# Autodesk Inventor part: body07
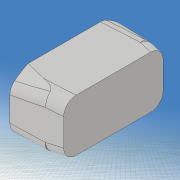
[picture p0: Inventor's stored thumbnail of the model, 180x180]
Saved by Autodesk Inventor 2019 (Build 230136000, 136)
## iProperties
Created: 2020-12
Part Number: body07
Material: 一般
Document SubType Name: Modeling
Designer: kikut
Density: 1 g/cm^3
Appearance: 既定
Mass: 87.6477 g
Surface Area: 156.124 cm^2
Volume: 87.6477 cm^3
Author: kikut
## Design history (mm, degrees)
sketch "スケッチ1"
  geometry: L1 (-100, -20)-(100, -20); L2 (100, -20)-(100, 20); L3 (100, 20)-(-100, 20); L4 (-100, 20)-(-100, -20); L5 (-100, -20)-(100, 20); L6 (100, -20)-(-100, 20); 1 further point
  constraints: 12 end point, 2 midpoint, 2 parallel, 1 horizontal, 1 perpendicular
  dimensions: "d0" = 40 distance of L3.end L1.start; "d1" = 200 distance of L2.end L3.end
extrude "押し出し1" new body sketch "スケッチ1" stored distance "d2" = 60; taper "d3" = 0 deg
sketch "スケッチ2"
  geometry: L1 (0, -60)-(0, 0) reference; L2 (200, -60)-(200, 0) reference; L3 (0, 0)-(200, 0) reference; L4 (200, -60)-(0, -60) reference; L5 (0, -26)-(0, -32); L6 (194, -10)-(194, -13); L7 (194, -13)-(174, -33); L8 (174, -33)-(200, -58); L9 (-20, 20)-(220, 20); L10 (220, 20)-(220, -100); L11 (220, -100)-(-20, -100); L12 (-20, -100)-(-20, 20); 12 further points
  constraints: 16 end point, 4 point on line, 2 parallel, 2 vertical, 1 horizontal, 1 perpendicular, 14 other
  dimensions: "d4" = 32 distance from line of point (32, -12) L1; "d5" = 50 horizontal distance of point (32, -12) point (82, -11); "d6" = 50 horizontal distance of point (132, -17) point (82, -11); "d7" = 12 distance from line of point (32, -12) L3; "d8" = 11 distance from line of point (82, -11) L3; "d10" = 17 distance from line of point (132, -17) L3; "d11" = 26 distance from line of L5.start L3; "d12" = 0 distance from line of point (200, -60) L4; "d13" = 28 distance from line of L5.end L4; "d14" = 12 distance from line of point (28, -48) L4; "d15" = 10 distance from line of point (80, -50) L4; "d16" = 16 distance from line of point (130, -44) L4; "d17" = 28 distance from line of point (28, -48) L1; "d19" = 50 horizontal distance of point (130, -44) point (80, -50); "d20" = 80 distance from line of point (80, -50) L1; "d21" = 6 distance from line of L6.start L2; "d22" = 36 distance from line of point (164, -24) L2; "d23" = 24 distance from line of point (176, -20) L2; "d24" = 10 distance from line of L6.start L3; "d25" = 20 distance from line of point (176, -20) L3; "d26" = 24 distance from line of point (164, -24) L3; "d27" = 40 distance from line of point (160, -40) L2; "d28" = 25 distance from line of point (175, -47.5) L2; "d29" = 12.5 distance from line of point (175, -47.5) L4; "d30" = 20 distance from line of L4 point (160, -40); "d31" = 3 distance of L6.start L6.end; "d32" = 33 distance from line of L7.end L3; "d33" = 26 distance from line of L7.end L2; "d34" = 2 distance of L8.end L2.start; "d35" = 120 distance of L11.end L9.start; "d36" = 240 distance of L10.end L11.end; "d37" = 20 distance between parallel lines of L1 L12; "d38" = 20 distance between parallel lines of L3 L9
extrude "押し出し2" cut sketch "スケッチ2" extent not by distance; stored distance "d39" = 0.02; taper "d40" = 0 deg
sketch "スケッチ8"
  geometry: L1 (-100, -20)-(-100, 20) reference; L2 (100, 20)-(100, -20) reference; L3 (-142.805, 0)-(142.831, 0) reference; L4 (110, 30)-(-110, 30); L5 (-110, 30)-(-110, -30); L6 (-110, -30)-(110, -30); L7 (110, -30)-(110, 30); L8 (110, 30)-(-110, -30); L9 (-110, 30)-(110, -30); L10 (-100, -2)-(-100, 2); L11 (100, -3)-(100, 3); 7 further points
  constraints: 16 end point, 4 point on line, 2 midpoint, 2 parallel, 2 perpendicular, 1 collinear, 1 horizontal, 10 other
  dimensions: "d93" = 2 vertical distance of point (0, 0) L10.end; "d94" = 2 vertical distance of L10.start point (0, 0); "d95" = 35 distance from line of point (-65, -10) L1; "d96" = 0 horizontal distance of point (-65, 10) point (-65, -10); "d97" = 10 vertical distance of point (0, 0) point (-65, -10); "d98" = 10 vertical distance of point (-65, 10) point (0, 0); "d99" = 100 distance from line of point (0, -10) L1; "d100" = 0 horizontal distance of point (0, 10) point (0, -10); "d101" = 10 distance of point (0, -10) point (0, 0); "d102" = 10 distance of point (0, 0) point (0, 10); "d103" = 160 distance from line of point (60, -4) L1; "d104" = 0 horizontal distance of point (60, 4) point (60, -4); "d105" = 4 distance from line of L3 point (60, -4); "d106" = 4 distance from line of L3 point (60, 4); "d107" = 3 distance from line of L11.start L3; "d108" = 3 distance from line of L11.end L3; "d109" = 220 distance of L5.end L6.end; "d110" = 60 distance of L4.end L5.end
extrude "押し出し6" cut sketch "スケッチ8" extent not by distance; stored distance "d111" = 10; taper "d112" = 0 deg
sketch "スケッチ9" dims "d113" = 20, "d114" = 12
  geometry: L1 (-29, -18)-(21, -18); L2 (21, -18)-(21, 22); L3 (21, 22)-(-29, 22); L4 (-29, 22)-(-29, -18); L5 (-29, -18)-(21, 22); L6 (21, -18)-(-29, 22); 2 further points; 1 other entity
  constraints: 12 end point, 2 midpoint, 2 parallel, 1 coincident, 1 horizontal, 1 perpendicular, 2 other
  dimensions: "d115" = 50 distance of L2.end L3.end; "d116" = 40 distance of L1.end L2.end
extrude "押し出し7" cut sketch "スケッチ9" distance "d117" = 150; taper "d118" = 0 deg
fillet "フィレット4" dims "d119" = 4
fillet "フィレット5" dims "d120" = 4
fillet "フィレット6" dims "d121" = 2
node "作業平面2"
sketch "スケッチ10"
  geometry: L1 (0, -41.439)-(0, 38.458) reference; L2 (141.833, 0)-(-140.631, 0) reference; L3 (82.55, 12.983)-(81.45, -4.983); A1 r 9 centre (82, 4) between (82.55, 12.983) and (81.45, -4.983); 1 further point
  constraints: 2 end point, 2 point on circle, 1 centre point
  dimensions: "d123" = 82 distance from line of L1 A1.centre; "d124" = 4 distance from line of L2 A1.centre; "d125" = 9 radius of A1; "d126" = 180 deg dimension on A1.centre L3.end L3.start; "d127" = 90 deg dimension on L3.end point (0, 0) A1.centre
revolve "回転1" sketch "スケッチ10" stored, may be unused: angle "d128" = 90 deg
mirror "ミラー1"
sketch "スケッチ11"
  geometry: L1 (-5, 30)-(-20, 30); L2 (-20, 30)-(-20, -30); L3 (-20, -30)-(-5, -30); L4 (-5, -30)-(-5, 30); L5 (0, -40.648)-(0, 34.486) reference; L6 (140.69, 0)-(-139.196, 0) reference; L7 (120, 53.792)-(-120, 53.792); L8 (-120, 53.792)-(-120, -46.208); L9 (-120, -46.208)-(120, -46.208); L10 (120, -46.208)-(120, 53.792); 1 further point
  constraints: 16 end point, 4 parallel, 2 horizontal, 2 perpendicular, 2 other
  dimensions: "d130" = 15 distance of L1.start L1.end; "d131" = 60 distance of L3.end L1.start; "d132" = 100 distance of L9.end L7.start; "d133" = 240 distance of L7.start L7.end; "d137" = 20 distance between parallel lines of L2 L5
extrude "押し出し8" cut sketch "スケッチ11" stored distance "d134" = 40; taper "d135" = 0 deg
node "ソリッド1"
other parameters: "d122" = -1
